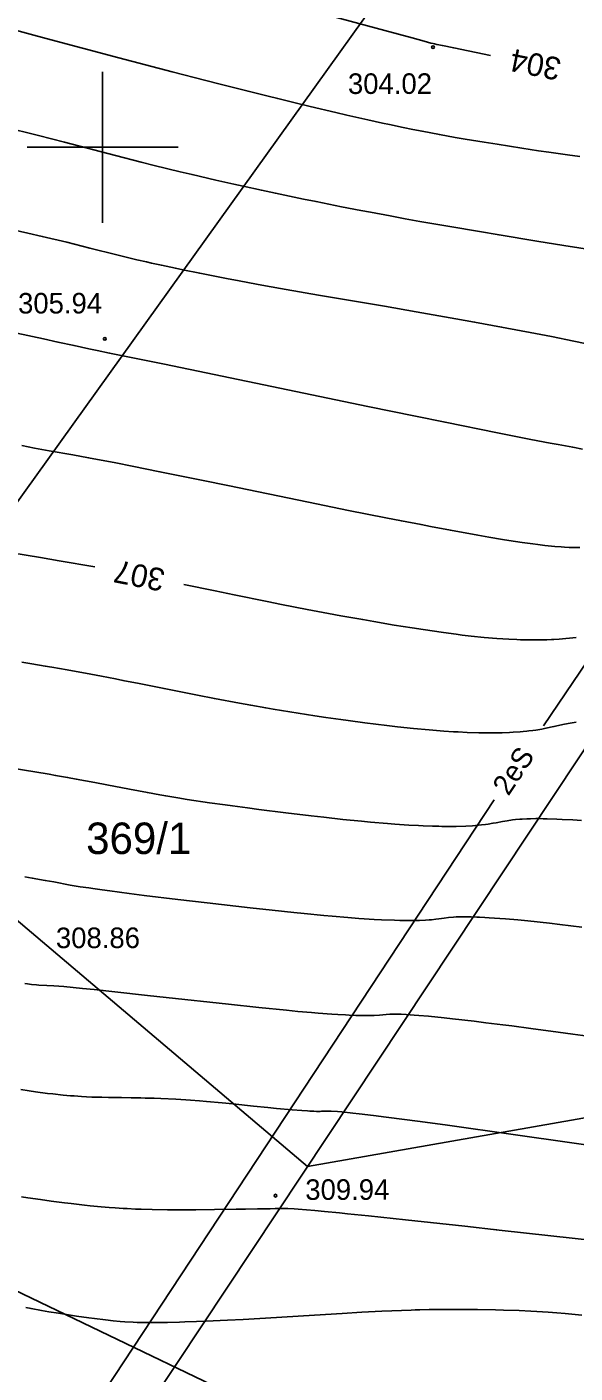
# Model space of a CAD drawing. Extents: x 7477803 to 7478145, y 5500698 to 5500984.
# Drawn here: x 7477847.5 to 7477865.63, y 5500809.46 to 5500853.98 of the extents above; entities that cross this region are included whole.
import ezdxf

# ---------------------------------------------------------------- set-up
doc = ezdxf.new("R2010")
doc.units = 0
for name, color, linetype in [('e_opisy', 7, 'Continuous'), ('eWN', 7, 'Continuous'), ('gr_dzialki', 7, 'Continuous'), ('gr_klasy', 7, 'Continuous'), ('nr_dzialki', 7, 'Continuous'), ('pkt_wys', 7, 'Continuous'), ('robocza49', 7, 'Continuous'), ('warst_ciagla', 7, 'Continuous'), ('warst_opis', 7, 'Continuous'), ('warst_pogrub', 7, 'Continuous'), ('warst_przeryw', 7, 'Continuous'), ('zakresy', 7, 'Continuous')]:
    doc.layers.add(name, color=color, linetype=linetype)

# ---------------------------------------------------------------- blocks, each defined once
blk = doc.blocks.new('801_3')
at = {"layer": 'pkt_wys'}
blk.add_circle((0, 0), 0.045, dxfattribs=at)
blk.add_circle((0, 0), 0.045, dxfattribs=at)

msp = doc.modelspace()

# ---------------------------------------------------------------- linework, layer by layer
at = {"layer": 'eWN'}
for points in [[(7477864.586, 5500830.869), (7477874.504, 5500845.51), (7477886.717, 5500863.094), (7477896.968, 5500876.013), (7477903.181, 5500887.651), (7477907.573, 5500896.009), (7477910.052, 5500901.721), (7477911.094, 5500907.132), (7477899.209, 5500916.554), (7477885.259, 5500927.591), (7477881.972, 5500929.954), (7477875.911, 5500934.547), (7477875.795, 5500934.654)], [(7477846.934, 5500804.11), (7477862.957, 5500828.422)]]:
    msp.add_lwpolyline(points, dxfattribs=at)
at = {"layer": 'gr_dzialki'}
for points in [[(7477867.48, 5500866.57), (7477829.72, 5500813.95)], [(7477876.54, 5500846.03), (7477848.298, 5500803.51)]]:
    msp.add_lwpolyline(points, dxfattribs=at)
at = {"layer": 'gr_klasy'}
for points in [[(7477856.78, 5500816.29), (7477819.732, 5500847.674)], [(7477899.58, 5500823.8), (7477856.78, 5500816.29)]]:
    msp.add_lwpolyline(points, dxfattribs=at)
at = {"layer": 'robocza49'}
for p, q in [((7477850, 5500847.5), (7477850, 5500852.5)), ((7477847.5, 5500850), (7477852.5, 5500850))]:
    msp.add_line(p, q, dxfattribs=at)
at = {"layer": 'warst_ciagla'}
for points in [[(7477847.433, 5500857.063), (7477851.692, 5500855.922), (7477856.593, 5500854.606), (7477859.335, 5500853.866), (7477860.246, 5500853.617), (7477860.646, 5500853.507), (7477860.865, 5500853.449), (7477860.935, 5500853.434), (7477860.985, 5500853.423), (7477861.055, 5500853.405), (7477861.246, 5500853.363), (7477861.62, 5500853.285), (7477862.839, 5500853.034)], [(7477865.883, 5500840.018), (7477865.559, 5500840.077), (7477865.076, 5500840.167), (7477864.813, 5500840.217), (7477864.168, 5500840.341), (7477863.064, 5500840.559), (7477861.334, 5500840.906), (7477860.359, 5500841.105), (7477858.78, 5500841.429), (7477855.603, 5500842.086), (7477852.047, 5500842.822), (7477850.229, 5500843.196), (7477849.825, 5500843.275), (7477849.541, 5500843.335), (7477849.054, 5500843.442), (7477848.521, 5500843.56), (7477848.041, 5500843.664), (7477846.268, 5500844.041)], [(7477821.865, 5500842.007), (7477825, 5500841.33), (7477826.512, 5500841), (7477828.785, 5500840.498), (7477830.32, 5500840.156), (7477833.526, 5500839.439), (7477837.092, 5500838.64), (7477838.836, 5500838.253), (7477840.437, 5500837.901), (7477841.096, 5500837.758), (7477841.927, 5500837.58), (7477842.321, 5500837.496), (7477843.155, 5500837.32), (7477844.16, 5500837.113), (7477844.621, 5500837.021), (7477845.266, 5500836.895), (7477845.864, 5500836.784), (7477846.147, 5500836.734), (7477846.422, 5500836.687), (7477846.995, 5500836.591), (7477847.943, 5500836.433), (7477848.56, 5500836.328), (7477849.745, 5500836.12)], [(7477852.689, 5500835.541), (7477853.728, 5500835.327), (7477854.351, 5500835.199), (7477855.445, 5500834.979), (7477855.924, 5500834.883), (7477856.764, 5500834.719), (7477857.472, 5500834.585), (7477857.885, 5500834.509), (7477858.61, 5500834.378), (7477858.977, 5500834.314), (7477859.647, 5500834.2), (7477860.243, 5500834.104), (7477860.608, 5500834.048), (7477861.28, 5500833.95), (7477861.699, 5500833.895), (7477861.902, 5500833.869), (7477862.198, 5500833.834), (7477862.628, 5500833.789), (7477863.041, 5500833.754), (7477863.243, 5500833.74), (7477863.442, 5500833.728), (7477863.703, 5500833.717), (7477863.832, 5500833.713), (7477864.085, 5500833.708), (7477864.415, 5500833.708), (7477864.577, 5500833.711), (7477864.697, 5500833.715), (7477864.855, 5500833.722), (7477864.933, 5500833.726), (7477865.107, 5500833.737), (7477865.334, 5500833.755), (7477865.446, 5500833.766), (7477865.666, 5500833.791)], [(7477865.847, 5500827.732), (7477865.561, 5500827.752), (7477865.202, 5500827.773), (7477865.033, 5500827.781), (7477864.714, 5500827.792), (7477864.581, 5500827.794), (7477864.412, 5500827.796), (7477864.331, 5500827.796), (7477864.158, 5500827.793), (7477864.035, 5500827.79), (7477863.882, 5500827.782), (7477863.81, 5500827.777), (7477863.659, 5500827.764), (7477863.565, 5500827.753), (7477863.391, 5500827.728), (7477863.229, 5500827.7), (7477863.022, 5500827.661), (7477862.918, 5500827.642), (7477862.756, 5500827.615), (7477862.67, 5500827.603), (7477862.535, 5500827.587), (7477862.34, 5500827.569), (7477862.237, 5500827.561), (7477862.019, 5500827.55), (7477861.703, 5500827.541), (7477861.534, 5500827.54), (7477861.403, 5500827.54), (7477861.222, 5500827.542), (7477861.129, 5500827.544), (7477860.913, 5500827.55), (7477860.611, 5500827.561), (7477860.454, 5500827.568), (7477860.128, 5500827.586), (7477859.668, 5500827.617), (7477859.428, 5500827.635), (7477858.861, 5500827.684), (7477858.565, 5500827.711), (7477857.951, 5500827.773), (7477857.322, 5500827.841), (7477856.9, 5500827.889), (7477856.067, 5500827.989), (7477855.173, 5500828.101), (7477854.792, 5500828.151), (7477854.3, 5500828.217), (7477854.061, 5500828.25), (7477853.54, 5500828.324), (7477852.802, 5500828.435), (7477852.491, 5500828.485), (7477852.091, 5500828.551), (7477851.899, 5500828.583), (7477851.481, 5500828.657), (7477850.894, 5500828.768), (7477850.136, 5500828.916), (7477849.746, 5500828.991), (7477849.128, 5500829.106), (7477848.84, 5500829.158), (7477848.442, 5500829.228), (7477848.237, 5500829.264), (7477847.762, 5500829.344), (7477847.013, 5500829.467)], [(7477847.429, 5500822.344), (7477847.519, 5500822.331), (7477847.649, 5500822.314), (7477847.812, 5500822.299), (7477847.889, 5500822.294), (7477848.157, 5500822.283), (7477848.382, 5500822.268), (7477848.715, 5500822.24), (7477849.337, 5500822.181), (7477849.725, 5500822.141), (7477850.403, 5500822.07), (7477851.485, 5500821.953), (7477852.103, 5500821.885), (7477854.162, 5500821.657), (7477855.175, 5500821.549), (7477856.088, 5500821.458), (7477856.459, 5500821.424), (7477856.918, 5500821.384), (7477857.133, 5500821.367), (7477857.581, 5500821.333), (7477857.786, 5500821.32), (7477858.04, 5500821.305), (7477858.159, 5500821.299), (7477858.381, 5500821.29), (7477858.641, 5500821.284), (7477858.757, 5500821.283), (7477858.837, 5500821.284), (7477858.936, 5500821.286), (7477858.981, 5500821.288), (7477859.162, 5500821.3), (7477859.382, 5500821.319), (7477859.506, 5500821.327), (7477859.652, 5500821.33), (7477859.736, 5500821.329), (7477859.88, 5500821.326), (7477860.048, 5500821.318), (7477860.312, 5500821.3), (7477860.46, 5500821.289), (7477860.789, 5500821.259), (7477861.298, 5500821.209), (7477861.581, 5500821.178), (7477862.291, 5500821.096), (7477862.684, 5500821.049), (7477863.245, 5500820.979), (7477863.543, 5500820.941), (7477864.171, 5500820.86), (7477865.078, 5500820.739), (7477865.56, 5500820.673), (7477866.718, 5500820.513)]]:
    msp.add_lwpolyline(points, dxfattribs=at)
at = {"layer": 'warst_pogrub'}
for points in [[(7477866.89, 5500846.495), (7477865.258, 5500846.753), (7477864.372, 5500846.897), (7477863.122, 5500847.102), (7477862.476, 5500847.21), (7477861.491, 5500847.377), (7477860.5, 5500847.551), (7477860.007, 5500847.639), (7477859.516, 5500847.729), (7477858.868, 5500847.85), (7477858.545, 5500847.911), (7477857.906, 5500848.034), (7477857.063, 5500848.202), (7477856.645, 5500848.287), (7477855.716, 5500848.481), (7477855.256, 5500848.579), (7477854.649, 5500848.712), (7477854.347, 5500848.779), (7477853.749, 5500848.914), (7477852.961, 5500849.097), (7477852.571, 5500849.19), (7477851.703, 5500849.402), (7477851.275, 5500849.509), (7477850.425, 5500849.726), (7477848.734, 5500850.165), (7477847.883, 5500850.386), (7477846.721, 5500850.68)], [(7477847.315, 5500815.294), (7477847.53, 5500815.26), (7477847.949, 5500815.198), (7477848.295, 5500815.149), (7477848.745, 5500815.09), (7477848.965, 5500815.064), (7477849.396, 5500815.015), (7477849.584, 5500814.996), (7477849.831, 5500814.972), (7477849.952, 5500814.961), (7477850.222, 5500814.939), (7477850.42, 5500814.924), (7477850.68, 5500814.907), (7477850.808, 5500814.9), (7477851.091, 5500814.886), (7477851.275, 5500814.879), (7477851.635, 5500814.869), (7477852.149, 5500814.861), (7477852.476, 5500814.86), (7477853.086, 5500814.864), (7477853.705, 5500814.869), (7477854.417, 5500814.877), (7477854.724, 5500814.881), (7477855.124, 5500814.888), (7477855.544, 5500814.897), (7477855.705, 5500814.901), (7477855.882, 5500814.907), (7477855.97, 5500814.907), (7477856.127, 5500814.904), (7477856.338, 5500814.892), (7477856.474, 5500814.882), (7477857.026, 5500814.835), (7477857.343, 5500814.805), (7477857.834, 5500814.758), (7477858.109, 5500814.73), (7477858.799, 5500814.659), (7477860.018, 5500814.531), (7477861.989, 5500814.317), (7477863.123, 5500814.192), (7477865.632, 5500813.912), (7477866.932, 5500813.764)], [(7477862.967, 5500814.209), (7477863.123, 5500814.192), (7477865.632, 5500813.912), (7477866.932, 5500813.764)]]:
    msp.add_lwpolyline(points, dxfattribs=at)
at = {"layer": 'warst_przeryw'}
for points in [[(7477865.797, 5500849.694), (7477865.389, 5500849.748), (7477864.769, 5500849.836), (7477864.427, 5500849.887), (7477863.874, 5500849.971), (7477863.061, 5500850.099), (7477862.623, 5500850.17), (7477862.002, 5500850.273), (7477861.671, 5500850.329), (7477861.143, 5500850.423), (7477860.57, 5500850.532), (7477860.263, 5500850.593), (7477859.943, 5500850.658), (7477859.494, 5500850.752), (7477859.259, 5500850.803), (7477858.772, 5500850.91), (7477858.082, 5500851.066), (7477857.72, 5500851.15), (7477856.865, 5500851.352), (7477856.415, 5500851.461), (7477855.794, 5500851.612), (7477855.474, 5500851.691), (7477854.814, 5500851.856), (7477853.895, 5500852.089), (7477853.419, 5500852.211), (7477852.305, 5500852.499), (7477850.541, 5500852.963), (7477848.128, 5500853.602), (7477846.948, 5500853.914)], [(7477846.702, 5500847.352), (7477847.525, 5500847.164), (7477848.001, 5500847.053), (7477848.817, 5500846.858), (7477849.579, 5500846.668), (7477850.467, 5500846.444), (7477850.908, 5500846.337), (7477851.136, 5500846.283), (7477851.452, 5500846.21), (7477851.614, 5500846.173), (7477851.948, 5500846.099), (7477852.412, 5500845.999), (7477852.652, 5500845.949), (7477853.213, 5500845.835), (7477854.105, 5500845.66), (7477854.521, 5500845.581), (7477855.096, 5500845.474), (7477855.391, 5500845.421), (7477856.075, 5500845.299), (7477857.147, 5500845.113), (7477859.328, 5500844.742), (7477860.371, 5500844.562), (7477861.684, 5500844.33), (7477862.309, 5500844.217), (7477863.205, 5500844.052), (7477864.323, 5500843.839), (7477864.85, 5500843.737), (7477865.598, 5500843.587), (7477866.925, 5500843.316)], [(7477847.323, 5500840.138), (7477847.748, 5500840.053), (7477848.229, 5500839.963), (7477849.018, 5500839.826), (7477849.537, 5500839.731), (7477850.437, 5500839.559), (7477850.976, 5500839.452), (7477851.896, 5500839.269), (7477853.332, 5500838.978), (7477854.139, 5500838.813), (7477856.808, 5500838.264), (7477858.14, 5500837.993), (7477859.374, 5500837.747), (7477859.888, 5500837.646), (7477860.538, 5500837.52), (7477860.848, 5500837.461), (7477861.511, 5500837.337), (7477862.414, 5500837.174), (7477862.779, 5500837.111), (7477863.232, 5500837.034), (7477863.445, 5500837), (7477863.886, 5500836.931), (7477864.239, 5500836.881), (7477864.403, 5500836.859), (7477864.637, 5500836.831), (7477864.966, 5500836.797), (7477865.176, 5500836.781), (7477865.28, 5500836.775), (7477865.434, 5500836.768), (7477865.589, 5500836.763), (7477865.795, 5500836.761)], [(7477847.326, 5500832.972), (7477847.655, 5500832.917), (7477848.1, 5500832.842), (7477848.324, 5500832.803), (7477848.833, 5500832.714), (7477849.61, 5500832.572), (7477849.96, 5500832.507), (7477850.432, 5500832.417), (7477850.67, 5500832.371), (7477851.211, 5500832.265), (7477852.033, 5500832.1), (7477853.144, 5500831.878), (7477853.701, 5500831.769), (7477854.535, 5500831.613), (7477854.905, 5500831.547), (7477855.398, 5500831.461), (7477855.644, 5500831.419), (7477856.197, 5500831.329), (7477857.025, 5500831.2), (7477857.392, 5500831.145), (7477857.881, 5500831.076), (7477858.125, 5500831.042), (7477858.673, 5500830.969), (7477859.401, 5500830.879), (7477859.76, 5500830.838), (7477860.29, 5500830.781), (7477860.803, 5500830.733), (7477861.052, 5500830.712), (7477861.296, 5500830.693), (7477861.611, 5500830.673), (7477861.765, 5500830.664), (7477862.064, 5500830.65), (7477862.448, 5500830.638), (7477862.632, 5500830.635), (7477862.768, 5500830.634), (7477862.944, 5500830.634), (7477863.031, 5500830.635), (7477863.221, 5500830.639), (7477863.466, 5500830.648), (7477863.585, 5500830.654), (7477863.814, 5500830.669), (7477863.912, 5500830.678), (7477864.04, 5500830.69), (7477864.103, 5500830.697), (7477864.241, 5500830.714), (7477864.341, 5500830.727), (7477864.47, 5500830.748), (7477864.533, 5500830.758), (7477864.671, 5500830.784), (7477864.936, 5500830.841), (7477865.289, 5500830.919), (7477865.474, 5500830.956), (7477865.671, 5500830.989)], [(7477865.859, 5500824.213), (7477865.126, 5500824.3), (7477864.783, 5500824.339), (7477864.069, 5500824.414), (7477863.742, 5500824.446), (7477863.337, 5500824.481), (7477863.148, 5500824.496), (7477862.796, 5500824.521), (7477862.651, 5500824.53), (7477862.469, 5500824.539), (7477862.383, 5500824.543), (7477862.2, 5500824.549), (7477862.073, 5500824.552), (7477861.917, 5500824.552), (7477861.845, 5500824.551), (7477861.697, 5500824.547), (7477861.608, 5500824.541), (7477861.448, 5500824.527), (7477861.303, 5500824.51), (7477861.122, 5500824.485), (7477861.031, 5500824.472), (7477860.886, 5500824.455), (7477860.808, 5500824.448), (7477860.68, 5500824.439), (7477860.491, 5500824.43), (7477860.389, 5500824.428), (7477860.168, 5500824.426), (7477859.84, 5500824.43), (7477859.662, 5500824.435), (7477859.227, 5500824.453), (7477858.991, 5500824.466), (7477858.658, 5500824.487), (7477858.483, 5500824.499), (7477858.118, 5500824.526), (7477857.597, 5500824.569), (7477857.323, 5500824.594), (7477856.67, 5500824.656), (7477856.326, 5500824.69), (7477855.613, 5500824.765), (7477854.884, 5500824.845), (7477853.46, 5500825.008), (7477852.495, 5500825.121), (7477851.374, 5500825.258), (7477850.883, 5500825.32), (7477850.237, 5500825.405), (7477849.984, 5500825.439), (7477849.678, 5500825.482), (7477849.54, 5500825.503), (7477849.262, 5500825.545), (7477848.926, 5500825.602), (7477848.388, 5500825.702), (7477848.388, 5500825.702), (7477848.102, 5500825.755), (7477847.67, 5500825.829), (7477847.432, 5500825.868)], [(7477867.702, 5500816.764), (7477865.525, 5500817.078), (7477863.586, 5500817.354), (7477861.418, 5500817.656), (7477860.513, 5500817.779), (7477859.379, 5500817.928), (7477858.961, 5500817.981), (7477858.486, 5500818.038), (7477858.284, 5500818.061), (7477857.915, 5500818.1), (7477857.774, 5500818.112), (7477857.567, 5500818.125), (7477857.432, 5500818.127), (7477857.366, 5500818.125), (7477857.289, 5500818.12), (7477857.249, 5500818.118), (7477857.2, 5500818.116), (7477857.124, 5500818.116), (7477857.083, 5500818.116), (7477856.992, 5500818.118), (7477856.855, 5500818.124), (7477856.78, 5500818.128), (7477856.594, 5500818.139), (7477856.27, 5500818.164), (7477855.758, 5500818.211), (7477855.467, 5500818.24), (7477854.991, 5500818.29), (7477854.308, 5500818.362), (7477853.959, 5500818.397), (7477853.44, 5500818.443), (7477853.211, 5500818.461), (7477852.909, 5500818.483), (7477852.758, 5500818.493), (7477852.422, 5500818.514), (7477851.923, 5500818.539), (7477851.703, 5500818.548), (7477851.412, 5500818.557), (7477851.268, 5500818.561), (7477850.944, 5500818.568), (7477850.624, 5500818.571), (7477850.194, 5500818.576), (7477849.976, 5500818.58), (7477849.642, 5500818.59), (7477849.471, 5500818.598), (7477849.297, 5500818.608), (7477849.059, 5500818.624), (7477848.938, 5500818.634), (7477848.691, 5500818.656), (7477848.352, 5500818.692), (7477848.179, 5500818.712), (7477847.779, 5500818.765), (7477847.574, 5500818.794), (7477847.296, 5500818.836)], [(7477865.859, 5500811.379), (7477865.307, 5500811.429), (7477865.028, 5500811.451), (7477864.746, 5500811.472), (7477864.367, 5500811.496), (7477864.175, 5500811.507), (7477863.789, 5500811.526), (7477863.267, 5500811.546), (7477863.003, 5500811.553), (7477862.401, 5500811.565), (7477862.097, 5500811.568), (7477861.687, 5500811.568), (7477861.48, 5500811.567), (7477861.063, 5500811.563), (7477860.5, 5500811.551), (7477860.216, 5500811.543), (7477859.568, 5500811.519), (7477859.241, 5500811.504), (7477858.583, 5500811.47), (7477857.926, 5500811.431), (7477856.651, 5500811.351), (7477855.754, 5500811.297), (7477854.649, 5500811.237), (7477854.135, 5500811.211), (7477853.413, 5500811.179), (7477853.111, 5500811.167), (7477852.725, 5500811.153), (7477852.541, 5500811.147), (7477852.143, 5500811.136), (7477851.809, 5500811.13), (7477851.645, 5500811.128), (7477851.397, 5500811.129), (7477851.142, 5500811.136), (7477851.01, 5500811.141), (7477850.732, 5500811.158), (7477850.584, 5500811.169), (7477850.35, 5500811.19), (7477850.099, 5500811.216), (7477849.737, 5500811.26), (7477849.544, 5500811.286), (7477849.135, 5500811.344), (7477848.542, 5500811.438), (7477848.224, 5500811.491), (7477847.976, 5500811.534), (7477847.634, 5500811.594), (7477847.458, 5500811.626)], [(7477865.859, 5500811.379), (7477865.307, 5500811.429), (7477865.028, 5500811.451), (7477864.746, 5500811.472), (7477864.367, 5500811.496), (7477864.175, 5500811.507), (7477863.789, 5500811.526), (7477863.267, 5500811.546), (7477863.003, 5500811.553), (7477862.401, 5500811.565), (7477862.178, 5500811.567), (7477861.877, 5500811.568), (7477861.726, 5500811.568), (7477861.422, 5500811.567), (7477861.013, 5500811.562), (7477860.807, 5500811.558), (7477860.339, 5500811.547)]]:
    msp.add_lwpolyline(points, dxfattribs=at)
at = {"layer": 'zakresy'}
msp.add_lwpolyline([(7477995.059, 5500962.348), (7477983.951, 5500968.084), (7477970.781, 5500968.613), (7477936.09, 5500958.171), (7477930.511, 5500954.336), (7477914.305, 5500958.58), (7477904.32, 5500957.41), (7477897.265, 5500950.868), (7477811.424, 5500829.338), (7477936.003, 5500769.492), (7478008.982, 5500726.585), (7478019.402, 5500721.781), (7478037.95, 5500734.97), (7478039.493, 5500755.094), (7478043.98, 5500765.708), (7478067.545, 5500795.068), (7478092.109, 5500820.25), (7478076.156, 5500837.989), (7478068.105, 5500851.146), (7478061.422, 5500873.298), (7478054.135, 5500876.371), (7478039.669, 5500897.644), (7478026.36, 5500915.23), (7478015.054, 5500927.728)], close=True, dxfattribs=at)

# ---------------------------------------------------------------- block references
at = {"layer": 'pkt_wys', "rotation": 0.0626175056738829}
for p in [(7477860.933, 5500853.314), (7477850.074, 5500843.662), (7477855.725, 5500815.328)]:
    msp.add_blockref('801_3', p, dxfattribs=at)

# ---------------------------------------------------------------- texts
at = {"layer": 'e_opisy'}
msp.add_text('2eS', height=0.68, rotation=56.6128, dxfattribs=at).set_placement((7477863.428, 5500828.519))
at = {"layer": 'nr_dzialki'}
msp.add_text('369/1', height=1.04, dxfattribs=at).set_placement((7477849.456, 5500826.627))
at = {"layer": 'pkt_wys'}
for s, p in [('304.02', (7477858.119, 5500851.764)), ('305.94', (7477847.203, 5500844.502)), ('308.86', (7477848.456, 5500823.514)), ('309.94', (7477856.708, 5500815.188))]:
    msp.add_text(s, height=0.68, rotation=0.0626, dxfattribs=at).set_placement(p)
at = {"layer": 'warst_opis'}
for s, rotation, p in [('304', 168.535, (7477865.218, 5500852.935)), ('307', 168.8772, (7477852.11, 5500836.037))]:
    msp.add_text(s, height=0.75, rotation=rotation, dxfattribs=at).set_placement(p)

doc.saveas('drawing.dxf')
